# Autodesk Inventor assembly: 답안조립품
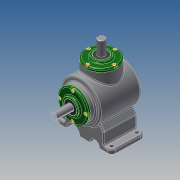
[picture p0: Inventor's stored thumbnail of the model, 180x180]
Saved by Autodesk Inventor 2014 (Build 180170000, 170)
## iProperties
Created: 2018-08
Part Number: 답안조립품
Document SubType Name: Assembly
Designer: kb542
Author: kb542
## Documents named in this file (14)
- C:\Users\kb542\Desktop\480807V1006\답안조립품.iam
- C:\Users\kb542\Desktop\480807V1006\본체.ipt
- C:\Users\kb542\Desktop\480807V1006\메인 베벨기어.ipt
- C:\Users\kb542\Desktop\480807V1006\메인 축.ipt
- 메인 축.ipt
- C:\Users\kb542\Desktop\480807V1006\베어링 6203.ipt
- C:\Users\kb542\Desktop\480807V1006\볼트 M4.ipt
- C:\Users\kb542\Desktop\480807V1006\서브 베벨기어.ipt
- C:\Users\kb542\Desktop\480807V1006\서브 축.ipt
- 서브 축.ipt
- C:\Users\kb542\Desktop\480807V1006\오일실 17 32 8.ipt
- C:\Users\kb542\Desktop\480807V1006\커버.ipt
- C:\Users\kb542\Desktop\480807V1006\키 4x4.ipt
- C:\Users\kb542\Desktop\480807V1006\키 5x5.ipt
